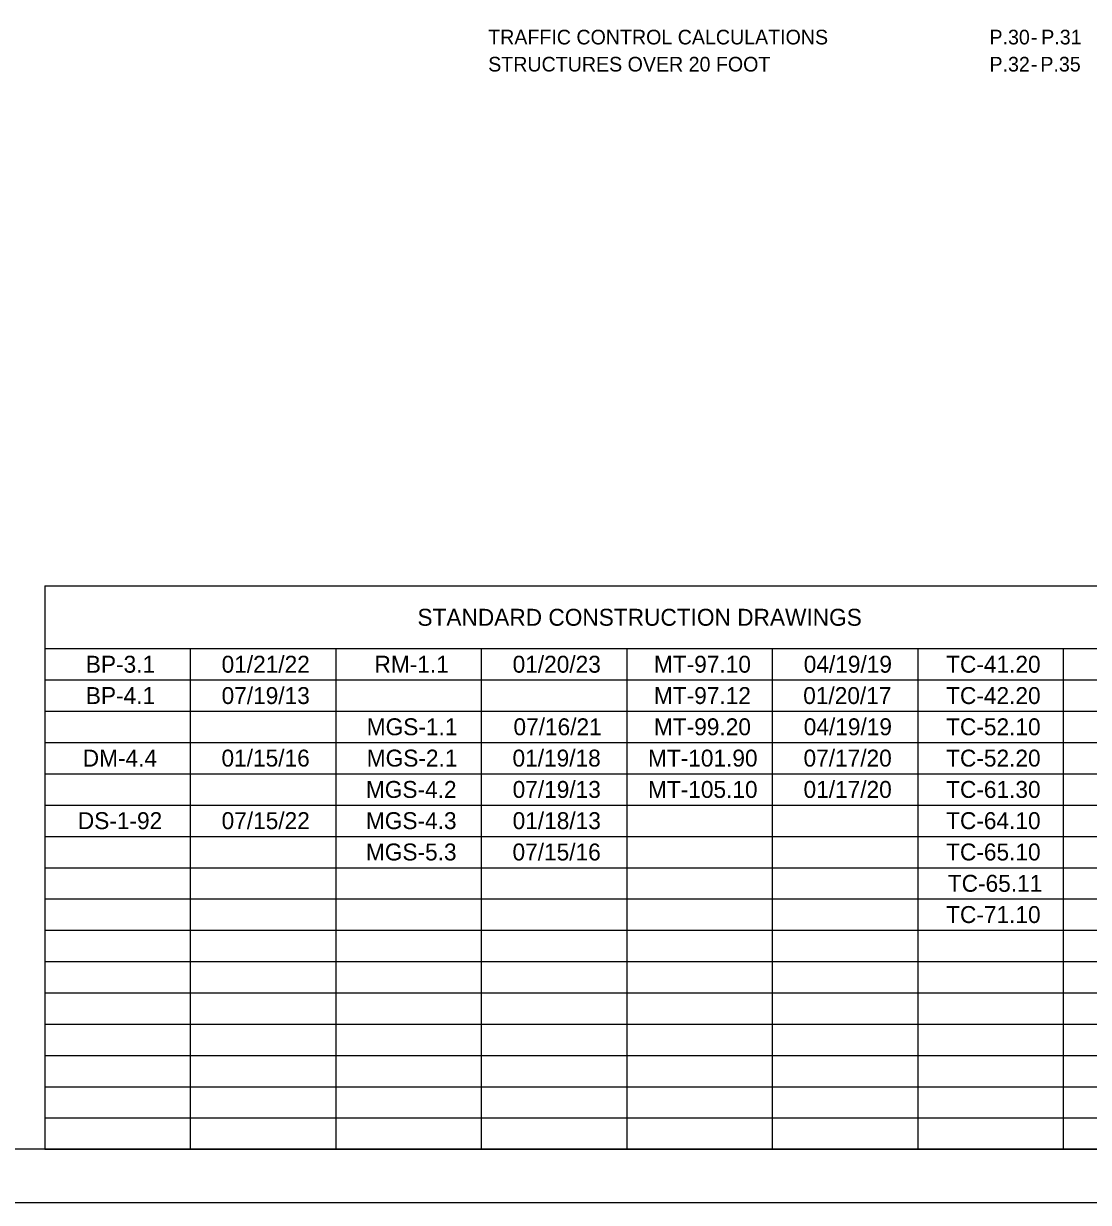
# Model space of a CAD drawing. Extents: x 0 to 34, y 0 to 22.
# Drawn here: x 9.95 to 19.97, y 0 to 11.1 of the extents above; entities that cross this region are included whole.
import ezdxf

# ---------------------------------------------------------------- set-up
doc = ezdxf.new("R2010")
doc.units = 0
for name, color, linetype in [('GM_X_County', 7, 'Continuous'), ('GM_X_Minor_Lake', 7, 'Continuous'), ('GM_X_Minor_River_Text', 7, 'Continuous')]:
    doc.layers.add(name, color=color, linetype=linetype)

msp = doc.modelspace()

# ---------------------------------------------------------------- linework, layer by layer
at = {"layer": 'GM_X_County'}
msp.add_lwpolyline([(0, 0), (34, 0), (34, 22), (0, 22)], close=True, dxfattribs=at)
at = {"layer": 'GM_X_Minor_Lake'}
for p, q in [((10.15, 5.805), (23.845, 5.805)), ((10.15, 5.805), (10.15, 0.5)), ((10.15, 5.215), (23.845, 5.215)), ((11.519, 5.215), (11.519, 0.5)), ((12.889, 5.215), (12.889, 0.5)), ((14.258, 5.215), (14.258, 0.5)), ((15.628, 5.215), (15.628, 0.5)), ((16.997, 5.215), (16.997, 0.5)), ((18.367, 5.215), (18.367, 0.5)), ((19.736, 5.215), (19.736, 0.5)), ((10.15, 4.921), (23.845, 4.921)), ((10.15, 4.626), (23.845, 4.626)), ((10.15, 4.331), (23.845, 4.331)), ((10.15, 4.036), (23.845, 4.036)), ((10.15, 3.742), (23.845, 3.742)), ((10.15, 3.447), (23.845, 3.447)), ((10.15, 3.152), (23.845, 3.152)), ((10.15, 2.858), (23.845, 2.858)), ((10.15, 2.563), (23.845, 2.563)), ((10.15, 2.268), (23.845, 2.268)), ((10.15, 1.974), (23.845, 1.974)), ((10.15, 1.679), (23.845, 1.679)), ((10.15, 1.384), (23.845, 1.384)), ((10.15, 1.089), (23.845, 1.089)), ((10.15, 0.795), (23.845, 0.795)), ((10.15, 0.5), (23.845, 0.5))]:
    msp.add_line(p, q, dxfattribs=at)
at = {"layer": 'GM_X_Minor_River_Text'}
msp.add_lwpolyline([(1.5, 21.5), (33.5, 21.5), (33.5, 0.5), (1.5, 0.5)], close=True, dxfattribs=at)

# ---------------------------------------------------------------- texts
at = {"layer": 'GM_X_Minor_Lake'}
for s, height, p in [('TRAFFIC CONTROL CALCULATIONS', 0.138, (14.323, 10.904)), ('P.30', 0.138, (19.041, 10.904)), ('P.31', 0.138, (19.528, 10.904)), ('-', 0.138, (19.431, 10.904)), ('STRUCTURES OVER 20 FOOT', 0.138, (14.323, 10.649)), ('P.32', 0.138, (19.041, 10.649)), ('P.35', 0.138, (19.52, 10.649)), ('-', 0.138, (19.431, 10.649)), ('STANDARD CONSTRUCTION DRAWINGS', 0.15949, (13.657, 5.43)), ('BP-3.1', 0.1595, (10.536, 4.988)), ('01/21/22', 0.1595, (11.814, 4.988)), ('RM-1.1', 0.1595, (13.253, 4.988)), ('01/20/23', 0.1595, (14.553, 4.988)), ('MT-97.10', 0.1595, (15.883, 4.988)), ('04/19/19', 0.1595, (17.293, 4.988)), ('TC-41.20', 0.1595, (18.633, 4.988)), ('BP-4.1', 0.1595, (10.536, 4.693)), ('07/19/13', 0.1595, (11.814, 4.693)), ('MT-97.12', 0.1595, (15.883, 4.693)), ('01/20/17', 0.1595, (17.288, 4.693)), ('TC-42.20', 0.1595, (18.633, 4.693)), ('MGS-1.1', 0.1595, (13.18, 4.399)), ('07/16/21', 0.1595, (14.561, 4.399)), ('MT-99.20', 0.1595, (15.883, 4.399)), ('04/19/19', 0.1595, (17.293, 4.399)), ('TC-52.10', 0.1595, (18.633, 4.399)), ('DM-4.4', 0.1595, (10.507, 4.104)), ('01/15/16', 0.1595, (11.813, 4.104)), ('MGS-2.1', 0.1595, (13.18, 4.104)), ('01/19/18', 0.1595, (14.552, 4.104)), ('MT-101.90', 0.1595, (15.827, 4.104)), ('07/17/20', 0.1595, (17.291, 4.104)), ('TC-52.20', 0.1595, (18.633, 4.104)), ('MGS-4.2', 0.1595, (13.172, 3.809)), ('07/19/13', 0.1595, (14.553, 3.809)), ('MT-105.10', 0.1595, (15.827, 3.809)), ('01/17/20', 0.1595, (17.291, 3.809)), ('TC-61.30', 0.1595, (18.633, 3.809)), ('DS-1-92', 0.1595, (10.461, 3.515)), ('07/15/22', 0.1595, (11.814, 3.515)), ('MGS-4.3', 0.1595, (13.172, 3.515)), ('01/18/13', 0.1595, (14.553, 3.515)), ('TC-64.10', 0.1595, (18.633, 3.515)), ('MGS-5.3', 0.1595, (13.172, 3.22)), ('07/15/16', 0.1595, (14.552, 3.22)), ('TC-65.10', 0.1595, (18.633, 3.22)), ('TC-65.11', 0.1595, (18.649, 2.925)), ('TC-71.10', 0.1595, (18.633, 2.631))]:
    msp.add_text(s, height=height, dxfattribs=at).set_placement(p)

doc.saveas('drawing.dxf')
